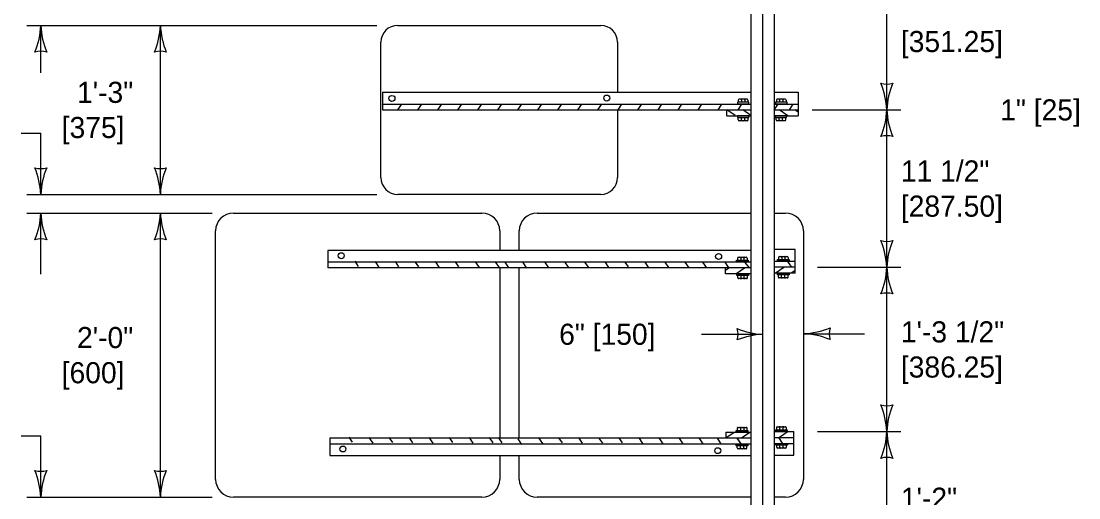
# Model space of a CAD drawing. Extents: x 49991.4 to 50021, y 49987.6 to 50011.4.
# Drawn here: x 50005.647 to 50008.653, y 49990.912 to 49992.268 of the extents above; entities that cross this region are included whole.
import ezdxf

# ---------------------------------------------------------------- set-up
doc = ezdxf.new("R2010")
doc.units = 0
for name, color, linetype in [('Level 1', 7, 'Continuous'), ('Level 2', 7, 'Continuous'), ('Level 3', 7, 'Continuous'), ('Level 4', 7, 'Continuous')]:
    doc.layers.add(name, color=color, linetype=linetype)

msp = doc.modelspace()

# ---------------------------------------------------------------- linework, layer by layer
at = {"layer": 'Level 1'}
for p, q in [((50007.7209, 49993.1079), (50007.721, 49988.4948)), ((50007.7873, 49993.1079), (50007.7873, 49988.4948)), ((50006.7171, 49992.2557), (50007.2938, 49992.2557)), ((50006.669, 49991.8232), (50006.669, 49992.2077)), ((50007.3419, 49992.2077), (50007.3419, 49992.0654)), ((50006.6733, 49992.0654), (50007.7198, 49992.0654)), ((50006.6733, 49992.0654), (50006.6733, 49992.0155)), ((50007.7872, 49992.0654), (50007.8549, 49992.0654)), ((50007.8549, 49992.0654), (50007.8549, 49991.9988)), ((50006.6733, 49992.0322), (50007.7209, 49992.0322)), ((50006.6733, 49992.0297), (50006.6745, 49992.0316)), ((50006.7175, 49992.0155), (50006.7284, 49992.0316)), ((50006.7744, 49992.0155), (50006.7853, 49992.0316)), ((50006.8313, 49992.0155), (50006.8422, 49992.0316)), ((50006.8381, 49992.0297), (50006.8393, 49992.0316)), ((50006.8409, 49992.0297), (50006.8421, 49992.0316)), ((50006.8881, 49992.0155), (50006.899, 49992.0316)), ((50006.9449, 49992.0155), (50006.9558, 49992.0316)), ((50007.0018, 49992.0155), (50007.0127, 49992.0316)), ((50007.0587, 49992.0155), (50007.0696, 49992.0316)), ((50007.0683, 49992.0297), (50007.0695, 49992.0316)), ((50007.1155, 49992.0155), (50007.1264, 49992.0316)), ((50007.1724, 49992.0155), (50007.1833, 49992.0316)), ((50007.2292, 49992.0155), (50007.2401, 49992.0316)), ((50007.2861, 49992.0155), (50007.2971, 49992.0316)), ((50007.343, 49992.0155), (50007.354, 49992.0316)), ((50007.3526, 49992.0297), (50007.3539, 49992.0316)), ((50007.3998, 49992.0155), (50007.4108, 49992.0316)), ((50007.4567, 49992.0155), (50007.4677, 49992.0316)), ((50007.5136, 49992.0155), (50007.5245, 49992.0316)), ((50007.5705, 49992.0155), (50007.5814, 49992.0316)), ((50007.6274, 49992.0155), (50007.6383, 49992.0316)), ((50007.6842, 49992.0155), (50007.6951, 49992.0316)), ((50007.6847, 49992.0434), (50007.6847, 49992.0372)), ((50007.7098, 49992.046), (50007.6872, 49992.046)), ((50007.7099, 49992.046), (50007.6872, 49992.046)), ((50007.694, 49992.046), (50007.694, 49992.0372)), ((50007.7033, 49992.046), (50007.7033, 49992.0372)), ((50007.7124, 49992.0434), (50007.7124, 49992.0372)), ((50007.7872, 49992.0322), (50007.8549, 49992.0322)), ((50007.7872, 49992.0155), (50007.7981, 49992.0316)), ((50007.7931, 49992.0434), (50007.7931, 49992.0372)), ((50007.8181, 49992.046), (50007.7955, 49992.046)), ((50007.8182, 49992.046), (50007.7955, 49992.046)), ((50007.8023, 49992.046), (50007.8023, 49992.0372)), ((50007.8116, 49992.046), (50007.8116, 49992.0372)), ((50007.8207, 49992.0434), (50007.8207, 49992.0372)), ((50007.8301, 49992.0153), (50007.841, 49992.0314)), ((50006.6733, 49992.0155), (50007.6523, 49992.0155)), ((50007.3419, 49992.0155), (50007.6523, 49992.0155)), ((50007.3419, 49992.0155), (50007.3419, 49991.8232)), ((50007.6523, 49992.0155), (50007.7204, 49992.0155)), ((50007.6523, 49992.0155), (50007.7211, 49992.0155)), ((50007.6523, 49991.9988), (50007.6523, 49992.0152)), ((50007.6761, 49991.9991), (50007.6523, 49992.0152)), ((50007.6523, 49991.9988), (50007.7209, 49991.9988)), ((50007.7209, 49991.9995), (50007.6976, 49992.0153)), ((50007.7872, 49992.0155), (50007.8549, 49992.0155)), ((50007.7873, 49991.9988), (50007.8549, 49991.9988)), ((50007.7881, 49992.0155), (50007.8549, 49992.0155)), ((50007.8254, 49991.9987), (50007.8009, 49992.0153)), ((50007.8549, 49992.0094), (50007.8457, 49992.0156)), ((50007.6849, 49991.9874), (50007.6849, 49991.9936)), ((50007.6874, 49991.9849), (50007.7101, 49991.9849)), ((50007.6875, 49991.9849), (50007.7101, 49991.9849)), ((50007.6941, 49991.9849), (50007.6941, 49991.9936)), ((50007.7034, 49991.9849), (50007.7034, 49991.9936)), ((50007.7126, 49991.9874), (50007.7126, 49991.9936)), ((50007.7922, 49991.9875), (50007.7922, 49991.9937)), ((50007.7947, 49991.985), (50007.8174, 49991.985)), ((50007.7948, 49991.985), (50007.8174, 49991.985)), ((50007.8013, 49991.985), (50007.8013, 49991.9937)), ((50007.8106, 49991.985), (50007.8106, 49991.9937)), ((50007.8198, 49991.9875), (50007.8198, 49991.9937)), ((50007.2938, 49991.7751), (50006.7171, 49991.7751)), ((50006.2498, 49991.7219), (50006.9563, 49991.7219)), ((50007.1129, 49991.7219), (50007.7209, 49991.7219)), ((50007.7873, 49991.7219), (50007.8194, 49991.7219)), ((50006.1993, 49990.9649), (50006.1993, 49991.6715)), ((50007.0068, 49991.6715), (50007.0068, 49991.6161)), ((50007.0624, 49991.6161), (50007.0624, 49991.6715)), ((50007.8699, 49991.6715), (50007.8699, 49990.9649)), ((50006.5183, 49991.6161), (50006.5183, 49991.5661)), ((50007.7209, 49991.6161), (50006.5183, 49991.6161)), ((50007.8462, 49991.6181), (50007.7877, 49991.6181)), ((50007.8462, 49991.5514), (50007.8462, 49991.6181)), ((50007.7209, 49991.5828), (50006.5183, 49991.5828)), ((50006.5948, 49991.585), (50006.6049, 49991.5701)), ((50006.6524, 49991.5839), (50006.6633, 49991.5676)), ((50006.7093, 49991.584), (50006.7194, 49991.5691)), ((50006.7669, 49991.5828), (50006.7763, 49991.5689)), ((50006.823, 49991.5839), (50006.8337, 49991.568)), ((50006.8803, 49991.5835), (50006.8896, 49991.5696)), ((50006.8803, 49991.5835), (50006.8896, 49991.5696)), ((50006.8803, 49991.5835), (50006.8896, 49991.5696)), ((50006.9371, 49991.5834), (50006.948, 49991.5672)), ((50006.994, 49991.5835), (50007.0041, 49991.5686)), ((50007.0211, 49991.5824), (50007.0305, 49991.5684)), ((50007.0722, 49991.582), (50007.0831, 49991.5657)), ((50007.1345, 49991.583), (50007.1454, 49991.5668)), ((50007.1914, 49991.5831), (50007.2015, 49991.5682)), ((50007.249, 49991.582), (50007.2584, 49991.568)), ((50007.3051, 49991.583), (50007.3159, 49991.5672)), ((50007.3624, 49991.5827), (50007.3717, 49991.5688)), ((50007.3624, 49991.5827), (50007.3717, 49991.5688)), ((50007.3624, 49991.5827), (50007.3717, 49991.5688)), ((50007.4192, 49991.5826), (50007.4301, 49991.5663)), ((50007.4761, 49991.5827), (50007.4862, 49991.5677)), ((50007.5328, 49991.5828), (50007.5439, 49991.5661)), ((50007.5828, 49991.5828), (50007.5941, 49991.5661)), ((50007.6467, 49991.5821), (50007.6561, 49991.5682)), ((50007.6467, 49991.5821), (50007.6561, 49991.5682)), ((50007.6467, 49991.5821), (50007.6575, 49991.5661)), ((50007.6826, 49991.5941), (50007.6826, 49991.5879)), ((50007.685, 49991.5966), (50007.7077, 49991.5966)), ((50007.6851, 49991.5966), (50007.7077, 49991.5966)), ((50007.6917, 49991.5966), (50007.6917, 49991.5879)), ((50007.701, 49991.5966), (50007.701, 49991.5879)), ((50007.7036, 49991.582), (50007.7161, 49991.5661)), ((50007.7102, 49991.5941), (50007.7102, 49991.5879)), ((50007.8462, 49991.5848), (50007.7873, 49991.5848)), ((50007.799, 49991.596), (50007.799, 49991.5899)), ((50007.8015, 49991.5986), (50007.8242, 49991.5986)), ((50007.8016, 49991.5986), (50007.8242, 49991.5986)), ((50007.8082, 49991.5986), (50007.8082, 49991.5899)), ((50007.8175, 49991.5986), (50007.8175, 49991.5899)), ((50007.8251, 49991.5846), (50007.8361, 49991.5681)), ((50007.8251, 49991.5846), (50007.8351, 49991.5696)), ((50007.8251, 49991.5846), (50007.8351, 49991.5696)), ((50007.8267, 49991.596), (50007.8267, 49991.5899)), ((50007.6484, 49991.5661), (50006.5183, 49991.5661)), ((50007.0068, 49991.5661), (50007.0068, 49991.0828)), ((50007.0624, 49991.0828), (50007.0624, 49991.5661)), ((50007.6484, 49991.56), (50007.6576, 49991.5662)), ((50007.7161, 49991.5661), (50007.6484, 49991.5661)), ((50007.7209, 49991.5661), (50007.6484, 49991.5661)), ((50007.6484, 49991.5494), (50007.6484, 49991.566)), ((50007.7209, 49991.5494), (50007.6484, 49991.5494)), ((50007.6778, 49991.5493), (50007.7023, 49991.5659)), ((50007.8462, 49991.5514), (50007.7873, 49991.5514)), ((50007.8462, 49991.5681), (50007.7887, 49991.5681)), ((50007.7895, 49991.5514), (50007.8139, 49991.5679)), ((50007.8462, 49991.5681), (50007.7911, 49991.5681)), ((50007.8462, 49991.5681), (50007.7911, 49991.5681)), ((50007.8462, 49991.5681), (50007.7925, 49991.5681)), ((50007.7988, 49991.5401), (50007.7988, 49991.5463)), ((50007.8081, 49991.5375), (50007.8081, 49991.5463)), ((50007.8174, 49991.5375), (50007.8174, 49991.5463)), ((50007.8265, 49991.5401), (50007.8265, 49991.5463)), ((50007.8353, 49991.5518), (50007.8454, 49991.5585)), ((50007.6834, 49991.5382), (50007.6834, 49991.5444)), ((50007.7085, 49991.5356), (50007.6859, 49991.5356)), ((50007.7086, 49991.5356), (50007.6859, 49991.5356)), ((50007.6926, 49991.5356), (50007.6926, 49991.5444)), ((50007.7019, 49991.5356), (50007.7019, 49991.5444)), ((50007.7111, 49991.5382), (50007.7111, 49991.5444)), ((50007.8239, 49991.5375), (50007.8013, 49991.5375)), ((50007.824, 49991.5375), (50007.8013, 49991.5375)), ((50007.6493, 49991.0988), (50007.6493, 49991.0824)), ((50007.6493, 49991.0988), (50007.7209, 49991.0988)), ((50007.6732, 49991.0984), (50007.6493, 49991.0824)), ((50007.682, 49991.1101), (50007.682, 49991.104)), ((50007.6845, 49991.1127), (50007.7072, 49991.1127)), ((50007.6846, 49991.1127), (50007.7072, 49991.1127)), ((50007.6911, 49991.1127), (50007.6911, 49991.104)), ((50007.7171, 49991.0976), (50007.6953, 49991.0828)), ((50007.7004, 49991.1127), (50007.7004, 49991.104)), ((50007.7096, 49991.1101), (50007.7096, 49991.104)), ((50007.7873, 49991.1007), (50007.8426, 49991.1007)), ((50007.7932, 49991.1119), (50007.7932, 49991.1058)), ((50007.7957, 49991.1145), (50007.8184, 49991.1145)), ((50007.7958, 49991.1145), (50007.8184, 49991.1145)), ((50007.8265, 49991.1008), (50007.802, 49991.0842)), ((50007.8024, 49991.1145), (50007.8024, 49991.1058)), ((50007.8117, 49991.1145), (50007.8117, 49991.1058)), ((50007.8209, 49991.1119), (50007.8209, 49991.1058)), ((50007.8426, 49991.034), (50007.8426, 49991.1007)), ((50006.524, 49991.0828), (50006.524, 49991.0328)), ((50006.524, 49991.0828), (50007.6493, 49991.0828)), ((50006.524, 49991.066), (50007.7209, 49991.066)), ((50006.5775, 49991.0852), (50006.5876, 49991.0703)), ((50006.6351, 49991.0841), (50006.646, 49991.0678)), ((50006.692, 49991.0842), (50006.7021, 49991.0693)), ((50006.7496, 49991.083), (50006.759, 49991.0691)), ((50006.8057, 49991.0841), (50006.8165, 49991.0682)), ((50006.863, 49991.0837), (50006.8723, 49991.0698)), ((50006.863, 49991.0837), (50006.8723, 49991.0698)), ((50006.863, 49991.0837), (50006.8723, 49991.0698)), ((50006.9198, 49991.0836), (50006.9307, 49991.0674)), ((50006.9767, 49991.0837), (50006.9868, 49991.0688)), ((50007.0038, 49991.0826), (50007.0132, 49991.0686)), ((50007.058, 49991.08), (50007.069, 49991.0638)), ((50007.1172, 49991.0832), (50007.1281, 49991.067)), ((50007.1741, 49991.0833), (50007.1842, 49991.0684)), ((50007.2317, 49991.0822), (50007.2411, 49991.0682)), ((50007.2878, 49991.0832), (50007.2986, 49991.0674)), ((50007.3451, 49991.0829), (50007.3544, 49991.069)), ((50007.3451, 49991.0829), (50007.3544, 49991.069)), ((50007.3451, 49991.0829), (50007.3544, 49991.069)), ((50007.4019, 49991.0828), (50007.4129, 49991.0666)), ((50007.4588, 49991.0828), (50007.4702, 49991.066)), ((50007.5157, 49991.0828), (50007.527, 49991.066)), ((50007.5726, 49991.0828), (50007.5839, 49991.066)), ((50007.6244, 49991.0821), (50007.6353, 49991.066)), ((50007.6244, 49991.0821), (50007.6353, 49991.066)), ((50007.6493, 49991.0828), (50007.7209, 49991.0828)), ((50007.6807, 49991.0828), (50007.6922, 49991.066)), ((50007.6812, 49991.0821), (50007.6922, 49991.066)), ((50007.6812, 49991.0821), (50007.6922, 49991.066)), ((50007.6812, 49991.0821), (50007.6922, 49991.066)), ((50007.6812, 49991.0821), (50007.6922, 49991.066)), ((50007.6812, 49991.0821), (50007.6922, 49991.066)), ((50007.7873, 49991.0673), (50007.8415, 49991.0673)), ((50007.7882, 49991.084), (50007.8426, 49991.084)), ((50007.7882, 49991.084), (50007.8415, 49991.084)), ((50007.7882, 49991.084), (50007.8415, 49991.084)), ((50007.7882, 49991.084), (50007.8405, 49991.084)), ((50007.7882, 49991.0673), (50007.8426, 49991.0673)), ((50007.799, 49991.084), (50007.81, 49991.0678)), ((50007.799, 49991.084), (50007.81, 49991.0678)), ((50007.799, 49991.084), (50007.81, 49991.0678)), ((50007.6818, 49991.0542), (50007.6818, 49991.0603)), ((50007.7069, 49991.0516), (50007.6843, 49991.0516)), ((50007.707, 49991.0516), (50007.6843, 49991.0516)), ((50007.691, 49991.0516), (50007.691, 49991.0603)), ((50007.7003, 49991.0516), (50007.7003, 49991.0603)), ((50007.7095, 49991.0542), (50007.7095, 49991.0603)), ((50007.7941, 49991.0561), (50007.7941, 49991.0622)), ((50007.8192, 49991.0535), (50007.7966, 49991.0535)), ((50007.8193, 49991.0535), (50007.7966, 49991.0535)), ((50007.8033, 49991.0535), (50007.8033, 49991.0622)), ((50007.8126, 49991.0535), (50007.8126, 49991.0622)), ((50007.8217, 49991.0561), (50007.8217, 49991.0622)), ((50006.524, 49991.0328), (50007.7209, 49991.0328)), ((50007.0068, 49991.0328), (50007.0068, 49990.9649)), ((50007.0624, 49990.9649), (50007.0624, 49991.0328)), ((50007.7882, 49991.034), (50007.8426, 49991.034)), ((50006.9563, 49990.9144), (50006.2498, 49990.9144)), ((50007.7209, 49990.9144), (50007.1129, 49990.9144)), ((50007.8194, 49990.9144), (50007.7873, 49990.9144))]:
    msp.add_line(p, q, dxfattribs=at)
for points in [[(50007.7151, 49992.0324), (50007.7151, 49992.037), (50007.6823, 49992.037), (50007.6823, 49992.0324)], [(50007.8235, 49992.0324), (50007.8235, 49992.037), (50007.7906, 49992.037), (50007.7906, 49992.0324)], [(50007.6822, 49991.9985), (50007.6822, 49991.9938), (50007.7151, 49991.9938), (50007.7151, 49991.9985)], [(50007.7894, 49991.9986), (50007.7894, 49991.9939), (50007.8223, 49991.9939), (50007.8223, 49991.9986)], [(50007.6798, 49991.583), (50007.6798, 49991.5877), (50007.7127, 49991.5877), (50007.7127, 49991.583)], [(50007.7963, 49991.585), (50007.7963, 49991.5897), (50007.8291, 49991.5897), (50007.8291, 49991.585)], [(50007.7138, 49991.5492), (50007.7138, 49991.5446), (50007.6809, 49991.5446), (50007.6809, 49991.5492)], [(50007.8292, 49991.5511), (50007.8292, 49991.5465), (50007.7964, 49991.5465), (50007.7964, 49991.5511)], [(50007.6792, 49991.0991), (50007.6792, 49991.1038), (50007.7121, 49991.1038), (50007.7121, 49991.0991)], [(50007.7905, 49991.1009), (50007.7905, 49991.1056), (50007.8234, 49991.1056), (50007.8234, 49991.1009)], [(50007.7122, 49991.0652), (50007.7122, 49991.0605), (50007.6793, 49991.0605), (50007.6793, 49991.0652)], [(50007.8245, 49991.0671), (50007.8245, 49991.0624), (50007.7916, 49991.0624), (50007.7916, 49991.0671)]]:
    msp.add_lwpolyline(points, close=True, dxfattribs=at)
for centre in [(50007.3112, 49992.0491), (50006.7005, 49992.0481), (50006.5564, 49991.6008), (50007.629, 49991.5987), (50006.5611, 49991.0513), (50007.6265, 49991.0464)]:
    msp.add_circle(centre, 0.00843, dxfattribs=at)
for centre, radius, start, end in [((50006.7171, 49992.2077), 0.0481, 90, 180), ((50007.2938, 49992.2077), 0.0481, 0, 90), ((50007.6873, 49992.0434), 0.00257, 90, 180), ((50007.6914, 49992.0434), 0.00257, 0, 90), ((50007.6965, 49992.0434), 0.00257, 90, 180), ((50007.7006, 49992.0434), 0.00257, 0, 90), ((50007.7057, 49992.0434), 0.00257, 90, 180), ((50007.7098, 49992.0434), 0.00257, 0, 90), ((50007.7956, 49992.0434), 0.00257, 90, 180), ((50007.7997, 49992.0434), 0.00257, 0, 90), ((50007.8048, 49992.0434), 0.00257, 90, 180), ((50007.8089, 49992.0434), 0.00257, 0, 90), ((50007.814, 49992.0434), 0.00257, 90, 180), ((50007.8181, 49992.0434), 0.00257, 0, 90), ((50007.6875, 49991.9874), 0.00257, 180, 270), ((50007.6916, 49991.9874), 0.00257, 270, 0), ((50007.6967, 49991.9874), 0.00257, 180, 270), ((50007.7008, 49991.9874), 0.00257, 270, 0), ((50007.7059, 49991.9874), 0.00257, 180, 270), ((50007.71, 49991.9874), 0.00257, 270, 0), ((50007.7948, 49991.9875), 0.00257, 180, 270), ((50007.7988, 49991.9875), 0.00257, 270, 0), ((50007.804, 49991.9875), 0.00257, 180, 270), ((50007.8081, 49991.9875), 0.00257, 270, 0), ((50007.8132, 49991.9875), 0.00257, 180, 270), ((50007.8173, 49991.9875), 0.00257, 270, 0), ((50006.7171, 49991.8232), 0.0481, 180, 270), ((50007.2938, 49991.8232), 0.0481, 270, 0), ((50006.2498, 49991.6715), 0.0505, 90, 180), ((50006.9563, 49991.6715), 0.0505, 0, 90), ((50007.1129, 49991.6715), 0.0505, 90, 180), ((50007.8194, 49991.6715), 0.0505, 0, 90), ((50007.6852, 49991.5941), 0.00257, 90, 180), ((50007.6892, 49991.5941), 0.00257, 0, 90), ((50007.6944, 49991.5941), 0.00257, 90, 180), ((50007.6984, 49991.5941), 0.00257, 0, 90), ((50007.7036, 49991.5941), 0.00257, 90, 180), ((50007.7076, 49991.5941), 0.00257, 0, 90), ((50007.8016, 49991.5961), 0.00257, 90, 180), ((50007.8057, 49991.5961), 0.00257, 0, 90), ((50007.8108, 49991.5961), 0.00257, 90, 180), ((50007.8149, 49991.5961), 0.00257, 0, 90), ((50007.82, 49991.5961), 0.00257, 90, 180), ((50007.8241, 49991.5961), 0.00257, 0, 90), ((50007.686, 49991.5382), 0.00257, 180, 270), ((50007.6901, 49991.5382), 0.00257, 270, 0), ((50007.6952, 49991.5382), 0.00257, 180, 270), ((50007.6993, 49991.5382), 0.00257, 270, 0), ((50007.7044, 49991.5382), 0.00257, 180, 270), ((50007.7085, 49991.5382), 0.00257, 270, 0), ((50007.8014, 49991.5401), 0.00257, 180, 270), ((50007.8055, 49991.5401), 0.00257, 270, 0), ((50007.8106, 49991.5401), 0.00257, 180, 270), ((50007.8147, 49991.5401), 0.00257, 270, 0), ((50007.8198, 49991.5401), 0.00257, 180, 270), ((50007.8239, 49991.5401), 0.00257, 270, 0), ((50007.6846, 49991.1102), 0.00257, 90, 180), ((50007.6886, 49991.1102), 0.00257, 0, 90), ((50007.6938, 49991.1102), 0.00257, 90, 180), ((50007.6979, 49991.1102), 0.00257, 0, 90), ((50007.703, 49991.1102), 0.00257, 90, 180), ((50007.7071, 49991.1102), 0.00257, 0, 90), ((50007.7958, 49991.112), 0.00257, 90, 180), ((50007.7999, 49991.112), 0.00257, 0, 90), ((50007.805, 49991.112), 0.00257, 90, 180), ((50007.8091, 49991.112), 0.00257, 0, 90), ((50007.8142, 49991.112), 0.00257, 90, 180), ((50007.8183, 49991.112), 0.00257, 0, 90), ((50007.6844, 49991.0541), 0.00257, 180, 270), ((50007.6884, 49991.0541), 0.00257, 270, 0), ((50007.6936, 49991.0541), 0.00257, 180, 270), ((50007.6977, 49991.0541), 0.00257, 270, 0), ((50007.7028, 49991.0541), 0.00257, 180, 270), ((50007.7069, 49991.0541), 0.00257, 270, 0), ((50007.7967, 49991.056), 0.00257, 180, 270), ((50007.8007, 49991.056), 0.00257, 270, 0), ((50007.8059, 49991.056), 0.00257, 180, 270), ((50007.8099, 49991.056), 0.00257, 270, 0), ((50007.8151, 49991.056), 0.00257, 180, 270), ((50007.8191, 49991.056), 0.00257, 270, 0), ((50006.2498, 49990.9649), 0.0505, 180, 270), ((50006.9563, 49990.9649), 0.0505, 270, 0), ((50007.1129, 49990.9649), 0.0505, 180, 270), ((50007.8194, 49990.9649), 0.0505, 270, 0)]:
    msp.add_arc(centre, radius, start, end, dxfattribs=at)
at = {"layer": 'Level 3'}
for p, q in [((50008.107, 49992.0155), (50008.107, 49992.5042)), ((50005.6624, 49992.2557), (50006.6571, 49992.2557)), ((50005.7024, 49992.1209), (50005.7024, 49992.2557)), ((50006.0424, 49991.7751), (50006.0424, 49992.2557)), ((50007.8949, 49992.0155), (50008.147, 49992.0155)), ((50008.107, 49991.5681), (50008.107, 49992.0155)), ((50005.6466, 49991.949), (50005.7024, 49991.949)), ((50005.7024, 49991.7756), (50005.7024, 49991.949)), ((50005.6624, 49991.7751), (50006.6571, 49991.7751)), ((50005.6624, 49991.7219), (50006.1898, 49991.7219)), ((50005.7024, 49991.5485), (50005.7024, 49991.7219)), ((50006.0424, 49990.9144), (50006.0424, 49991.7219)), ((50007.9099, 49991.5681), (50008.147, 49991.5681)), ((50008.107, 49991.1007), (50008.107, 49991.5681)), ((50007.5807, 49991.3775), (50007.7541, 49991.3775)), ((50007.8699, 49991.379), (50008.0433, 49991.379)), ((50007.9099, 49991.1007), (50008.147, 49991.1007)), ((50008.107, 49990.6217), (50008.107, 49991.1007)), ((50005.6466, 49991.0883), (50005.7024, 49991.0883)), ((50005.7024, 49990.9149), (50005.7024, 49991.0883)), ((50005.6624, 49990.9144), (50006.1898, 49990.9144))]:
    msp.add_line(p, q, dxfattribs=at)
for centre, radius, start, end in [((50005.4803, 49992.2649), 0.2223, 337.456, 357.6395), ((50005.9351, 49992.2672), 0.233, 182.8273, 202.0772), ((50005.8203, 49992.2649), 0.2223, 337.456, 357.6395), ((50006.2751, 49992.2672), 0.233, 182.8273, 202.0772), ((50005.7024, 49992.1275), 0.0548, 72.1388, 107.8612), ((50006.0424, 49992.1275), 0.0548, 72.1388, 107.8612), ((50008.107, 49992.1437), 0.0548, 252.1388, 287.8612), ((50007.8743, 49992.004), 0.233, 2.8273, 22.0772), ((50008.3291, 49992.0063), 0.2223, 157.456, 177.6395), ((50007.8849, 49992.0247), 0.2223, 337.456, 357.6395), ((50008.3397, 49992.027), 0.233, 182.8273, 202.0772), ((50008.107, 49991.8873), 0.0548, 72.1388, 107.8612), ((50005.7024, 49991.9033), 0.0548, 252.1388, 287.8612), ((50005.4697, 49991.7636), 0.233, 2.8273, 22.0772), ((50005.9245, 49991.7659), 0.2223, 157.456, 177.6395), ((50006.0424, 49991.9033), 0.0548, 252.1388, 287.8612), ((50005.8097, 49991.7636), 0.233, 2.8273, 22.0772), ((50006.2645, 49991.7659), 0.2223, 157.456, 177.6395), ((50005.4803, 49991.7311), 0.2223, 337.456, 357.6395), ((50005.9351, 49991.7334), 0.233, 182.8273, 202.0772), ((50005.8203, 49991.7311), 0.2223, 337.456, 357.6395), ((50006.2751, 49991.7334), 0.233, 182.8273, 202.0772), ((50005.7024, 49991.5937), 0.0548, 72.1388, 107.8612), ((50006.0424, 49991.5937), 0.0548, 72.1388, 107.8612), ((50008.107, 49991.6963), 0.0548, 252.1388, 287.8612), ((50007.8743, 49991.5566), 0.233, 2.8273, 22.0772), ((50008.3291, 49991.5589), 0.2223, 157.456, 177.6395), ((50007.8849, 49991.5773), 0.2223, 337.456, 357.6395), ((50008.3397, 49991.5796), 0.233, 182.8273, 202.0772), ((50008.107, 49991.4399), 0.0548, 72.1388, 107.8612), ((50007.8584, 49991.6117), 0.233, 272.8273, 292.0772), ((50007.9981, 49991.379), 0.0548, 162.1388, 197.8612), ((50007.7628, 49991.5885), 0.2112, 247.456, 267.6395), ((50007.6323, 49991.3775), 0.052, 342.1388, 17.8612), ((50007.765, 49991.1564), 0.2213, 92.8273, 112.0772), ((50007.8607, 49991.1569), 0.2223, 67.456, 87.6395), ((50008.107, 49991.2289), 0.0548, 252.1388, 287.8612), ((50007.8743, 49991.0892), 0.233, 2.8273, 22.0772), ((50008.3291, 49991.0915), 0.2223, 157.456, 177.6395), ((50007.8849, 49991.1099), 0.2223, 337.456, 357.6395), ((50008.3397, 49991.1122), 0.233, 182.8273, 202.0772), ((50008.107, 49990.9725), 0.0548, 72.1388, 107.8612), ((50005.7024, 49991.0426), 0.0548, 252.1388, 287.8612), ((50005.4697, 49990.9029), 0.233, 2.8273, 22.0772), ((50005.9245, 49990.9052), 0.2223, 157.456, 177.6395), ((50006.0424, 49991.0426), 0.0548, 252.1388, 287.8612), ((50005.8097, 49990.9029), 0.233, 2.8273, 22.0772), ((50006.2645, 49990.9052), 0.2223, 157.456, 177.6395)]:
    msp.add_arc(centre, radius, start, end, dxfattribs=at)
at = {"layer": 'Level 4'}
msp.add_line((50007.7541, 49993.1079), (50007.7541, 49990.2553), dxfattribs=at)

# ---------------------------------------------------------------- texts
at = {"layer": 'Level 2'}
for s, p in [('[351.25]', (50008.147, 49992.1799)), ('1\'-3"', (50005.8054, 49992.0354)), ('1" [25]', (50008.4293, 49991.9855)), ('[375]', (50005.7619, 49991.9354)), ('11 1/2"', (50008.147, 49991.8118)), ('[287.50]', (50008.147, 49991.7118)), ('2\'-0"', (50005.8054, 49991.3381)), ('6" [150]', (50007.1757, 49991.3475)), ('1\'-3 1/2"', (50008.147, 49991.3543)), ('[386.25]', (50008.147, 49991.2543)), ('[600]', (50005.7619, 49991.2381)), ('1\'-2"', (50008.147, 49990.8813))]:
    msp.add_text(s, height=0.06, dxfattribs=at).set_placement(p)

doc.saveas('drawing.dxf')
